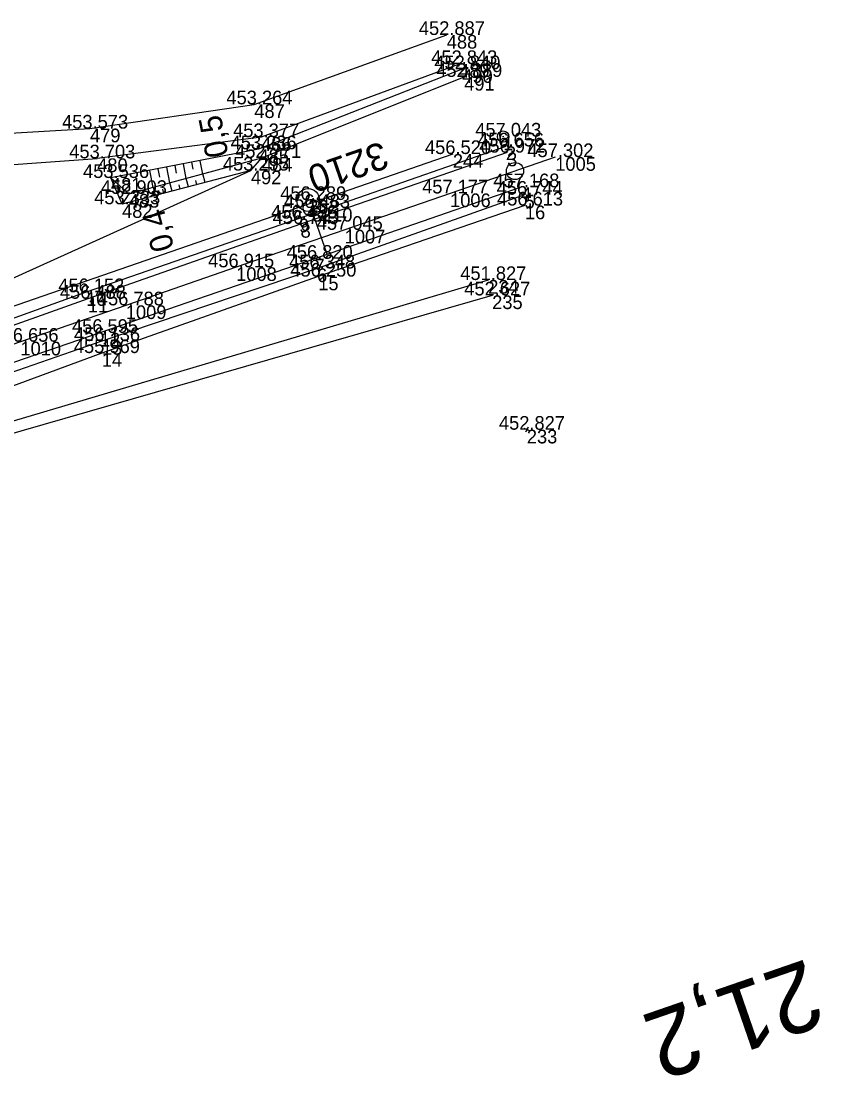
# Model space of a CAD drawing. Extents: x -751615 to -750797, y -1114905 to -1114561.
# Drawn here: x -750867.3 to -750797, y -1114657.1 to -1114564.4 of the extents above; entities that cross this region are included whole.
import ezdxf

# ---------------------------------------------------------------- set-up
doc = ezdxf.new("R2010")
doc.units = 0
for name, color, linetype in [('Vrstva 1', 7, 'Continuous'), ('Vrstva 4', 7, 'Continuous'), ('Vrstva 48', 7, 'Continuous'), ('Vrstva 49', 7, 'Continuous'), ('Vrstva 51', 7, 'Continuous'), ('Vrstva 60', 7, 'Continuous'), ('Vrstva 61', 7, 'Continuous'), ('Vrstva 63', 7, 'Continuous'), ('Vrstva 7', 7, 'Continuous')]:
    doc.layers.add(name, color=color, linetype=linetype)

msp = doc.modelspace()

# ---------------------------------------------------------------- linework, layer by layer
at = {"layer": 'Vrstva 1'}
msp.add_lwpolyline([(-750820.337, -1114576.326), (-750829.58, -1114579.518), (-750838.838, -1114582.712), (-750848.38, -1114586.005), (-750858.075, -1114589.346), (-750867.336, -1114592.541), (-750876.526, -1114595.715), (-750885.989, -1114598.98), (-750895.385, -1114602.229), (-750902.991, -1114604.843), (-750908.211, -1114606.647), (-750914.742, -1114608.898), (-750924.077, -1114612.114), (-750933.495, -1114615.368), (-750942.896, -1114618.61), (-750952.239, -1114621.829), (-750961.799, -1114625.127), (-750971.586, -1114628.505), (-750981.562, -1114631.945), (-750991.246, -1114635.286), (-751001.048, -1114638.665), (-751010.672, -1114641.989), (-751020.123, -1114645.246), (-751029.869, -1114648.612)], dxfattribs=at)
at = {"layer": 'Vrstva 4'}
for points in [[(-750824.673, -1114575.386), (-750842.852, -1114581.727), (-750861.561, -1114588.189), (-750880.945, -1114595.155), (-750899.361, -1114601.468), (-750902.908, -1114603.401)], [(-750824.563, -1114575.932), (-750842.715, -1114582.202), (-750861.411, -1114588.769), (-750880.904, -1114595.722), (-750899.175, -1114602.016), (-750902.908, -1114603.401)], [(-750823.32, -1114578.973), (-750841.487, -1114585.259), (-750860.348, -1114591.764), (-750879.972, -1114598.494), (-750898.231, -1114604.794), (-750901.922, -1114606.212)], [(-750823.034, -1114579.626), (-750841.271, -1114586.102), (-750860.173, -1114592.481), (-750879.743, -1114599.276), (-750897.921, -1114605.245), (-750901.922, -1114606.212)]]:
    msp.add_lwpolyline(points, dxfattribs=at)
at = {"layer": 'Vrstva 48'}
for p, q in [((-750853.039, -1114576.924), (-750852.79, -1114578.201)), ((-750852.302, -1114576.781), (-750852.183, -1114577.393)), ((-750851.566, -1114576.637), (-750851.338, -1114577.808)), ((-750855.983, -1114577.497), (-750855.693, -1114578.988)), ((-750855.247, -1114577.353), (-750855.107, -1114578.072)), ((-750854.511, -1114577.21), (-750854.242, -1114578.594)), ((-750853.775, -1114577.067), (-750853.645, -1114577.732)), ((-750851.11, -1114578.56), (-750851.308, -1114577.8)), ((-750854.013, -1114579.318), (-750854.204, -1114578.584)), ((-750853.287, -1114579.128), (-750853.384, -1114578.758)), ((-750852.561, -1114578.939), (-750852.756, -1114578.192)), ((-750851.836, -1114578.749), (-750851.934, -1114578.373)), ((-750855.464, -1114579.697), (-750855.652, -1114578.976)), ((-750854.738, -1114579.507), (-750854.833, -1114579.144))]:
    msp.add_line(p, q, dxfattribs=at)
at = {"layer": 'Vrstva 49'}
for p, q in [((-750857.81, -1114579.561), (-750846.11, -1114576.392)), ((-750822.608, -1114600.381), (-750823.058, -1114600.163)), ((-750822.724, -1114600.047), (-750822.942, -1114600.497))]:
    msp.add_line(p, q, dxfattribs=at)
for points in [[(-750828.513, -1114568.604), (-750846.414, -1114575.635), (-750859.378, -1114578.157)], [(-750902.869, -1114601.131), (-750876.43, -1114590.758), (-750847.082, -1114577.508), (-750846.11, -1114576.392), (-750828.341, -1114569.281)], [(-750829.333, -1114576.055), (-750875.877, -1114592.182), (-750902.869, -1114601.131)], [(-750847.082, -1114577.508), (-750858.403, -1114580.464), (-750859.378, -1114578.157)], [(-750859.378, -1114578.157), (-750857.81, -1114579.561), (-750858.403, -1114580.464)], [(-750823, -1114580.577), (-750841.163, -1114586.823), (-750860.183, -1114593.537), (-750879.382, -1114600.618), (-750897.603, -1114606.242), (-750900.708, -1114608.016), (-750901.423, -1114610.555), (-750897.925, -1114617.962)], [(-750826.229, -1114587.12), (-750875.492, -1114601.735), (-750898.314, -1114607.786)], [(-750825.879, -1114588.474), (-750875.252, -1114602.676), (-750897.922, -1114608.949)]]:
    msp.add_lwpolyline(points, dxfattribs=at)
at = {"layer": 'Vrstva 51'}
for points in [[(-750861.222, -1114573.82), (-750846.781, -1114571.689), (-750829.869, -1114565.596)], [(-750828.782, -1114568.15), (-750846.19, -1114574.573), (-750860.591, -1114576.435)], [(-750907.847, -1114605.676), (-750909.898, -1114596.967), (-750910.005, -1114587.848), (-750908.734, -1114583.94), (-750904.958, -1114578.749), (-750901.36, -1114576.145), (-750861.222, -1114573.82)], [(-750907.847, -1114605.676), (-750904.542, -1114604.506), (-750906.55, -1114596.602), (-750906.082, -1114588.417), (-750904.868, -1114585.385), (-750901.781, -1114581.531), (-750899.088, -1114579.21), (-750860.591, -1114576.435)]]:
    msp.add_lwpolyline(points, dxfattribs=at)
at = {"layer": 'Vrstva 60'}
for p, q in [((-750829.869, -1114565.596), (-750829.869, -1114565.596)), ((-750828.782, -1114568.15), (-750828.782, -1114568.15)), ((-750828.513, -1114568.604), (-750828.513, -1114568.604)), ((-750828.341, -1114569.281), (-750828.341, -1114569.281)), ((-750846.781, -1114571.689), (-750846.781, -1114571.689)), ((-750861.222, -1114573.82), (-750861.222, -1114573.82)), ((-750846.19, -1114574.573), (-750846.19, -1114574.573)), ((-750824.914, -1114574.521), (-750824.914, -1114574.521)), ((-750846.414, -1114575.635), (-750846.414, -1114575.635)), ((-750829.333, -1114576.055), (-750829.333, -1114576.055)), ((-750824.673, -1114575.386), (-750824.673, -1114575.386)), ((-750824.563, -1114575.932), (-750824.563, -1114575.932)), ((-750860.591, -1114576.435), (-750860.591, -1114576.435)), ((-750846.11, -1114576.392), (-750846.11, -1114576.392)), ((-750820.337, -1114576.326), (-750820.337, -1114576.326)), ((-750847.082, -1114577.508), (-750847.082, -1114577.508)), ((-750859.378, -1114578.157), (-750859.378, -1114578.157)), ((-750857.81, -1114579.561), (-750857.81, -1114579.561)), ((-750829.58, -1114579.518), (-750829.58, -1114579.518)), ((-750823.32, -1114578.973), (-750823.32, -1114578.973)), ((-750823.034, -1114579.626), (-750823.034, -1114579.626)), ((-750858.403, -1114580.464), (-750858.403, -1114580.464)), ((-750842.051, -1114580.092), (-750842.051, -1114580.092)), ((-750823, -1114580.577), (-750823, -1114580.577)), ((-750841.722, -1114580.791), (-750841.722, -1114580.791)), ((-750842.852, -1114581.727), (-750842.852, -1114581.727)), ((-750842.715, -1114582.202), (-750842.715, -1114582.202)), ((-750838.838, -1114582.712), (-750838.838, -1114582.712)), ((-750841.487, -1114585.259), (-750841.487, -1114585.259)), ((-750848.38, -1114586.005), (-750848.38, -1114586.005)), ((-750841.271, -1114586.102), (-750841.271, -1114586.102)), ((-750841.163, -1114586.823), (-750841.163, -1114586.823)), ((-750826.229, -1114587.12), (-750826.229, -1114587.12)), ((-750861.561, -1114588.189), (-750861.561, -1114588.189)), ((-750861.411, -1114588.769), (-750861.411, -1114588.769)), ((-750825.879, -1114588.474), (-750825.879, -1114588.474)), ((-750858.075, -1114589.346), (-750858.075, -1114589.346)), ((-750860.348, -1114591.764), (-750860.348, -1114591.764)), ((-750860.173, -1114592.481), (-750860.173, -1114592.481)), ((-750860.183, -1114593.537), (-750860.183, -1114593.537)), ((-750822.833, -1114600.272), (-750822.833, -1114600.272))]:
    msp.add_line(p, q, dxfattribs=at)
at = {"layer": 'Vrstva 63'}
for p, q in [((-750842.051, -1114580.092), (-750842.051, -1114580.092)), ((-750841.675, -1114580.775), (-750841.769, -1114580.807)), ((-750841.725, -1114581.037), (-750840.42, -1114584.818))]:
    msp.add_line(p, q, dxfattribs=at)
for centre, radius in [((-750842.051, -1114580.092), 1), ((-750841.722, -1114580.791), 0.756)]:
    msp.add_circle(centre, radius, dxfattribs=at)
at = {"layer": 'Vrstva 7'}
msp.add_line((-750824.867, -1114574.505), (-750824.961, -1114574.537), dxfattribs=at)
for centre, radius in [((-750824.914, -1114574.521), 0.5), ((-750823.872, -1114577.547), 0.75)]:
    msp.add_circle(centre, radius, dxfattribs=at)

# ---------------------------------------------------------------- texts
at = {"layer": 'Vrstva 48'}
for s, rotation, p in [('0,5', 101.00875, (-750849.039, -1114576.159)), ('0,4', 105.15521, (-750853.8, -1114584.322))]:
    msp.add_text(s, height=2, rotation=rotation, dxfattribs=at).set_placement(p)
at = {"layer": 'Vrstva 60'}
for s, p in [('488', (-750829.869, -1114566.796)), ('489', (-750828.782, -1114569.35)), ('490', (-750828.513, -1114569.804)), ('491', (-750828.341, -1114570.481)), ('487', (-750846.781, -1114572.889)), ('479', (-750861.222, -1114575.02)), ('486', (-750846.19, -1114575.773)), ('1', (-750824.914, -1114575.721)), ('485', (-750846.414, -1114576.835)), ('244', (-750829.333, -1114577.255)), ('2', (-750824.673, -1114576.586)), ('3', (-750824.563, -1114577.132)), ('480', (-750860.591, -1114577.635)), ('484', (-750846.11, -1114577.592)), ('1005', (-750820.337, -1114577.526)), ('492', (-750847.082, -1114578.708)), ('481', (-750859.378, -1114579.357)), ('483', (-750857.81, -1114580.761)), ('1006', (-750829.58, -1114580.718)), ('4', (-750823.32, -1114580.173)), ('5', (-750823.034, -1114580.826)), ('482', (-750858.403, -1114581.664)), ('232', (-750842.051, -1114581.292)), ('16', (-750823, -1114581.777)), ('3210', (-750841.722, -1114581.991)), ('9', (-750842.852, -1114582.927)), ('8', (-750842.715, -1114583.402)), ('1007', (-750838.838, -1114583.912)), ('7', (-750841.487, -1114586.459)), ('1008', (-750848.38, -1114587.205)), ('6', (-750841.271, -1114587.302)), ('15', (-750841.163, -1114588.023)), ('234', (-750826.229, -1114588.32)), ('10', (-750861.561, -1114589.389)), ('11', (-750861.411, -1114589.969)), ('235', (-750825.879, -1114589.674)), ('1009', (-750858.075, -1114590.546)), ('12', (-750860.348, -1114592.964)), ('1010', (-750867.336, -1114593.741)), ('13', (-750860.173, -1114593.681)), ('14', (-750860.183, -1114594.737)), ('233', (-750822.833, -1114601.472))]:
    msp.add_text(s, height=1.2, dxfattribs=at).set_placement(p)
at = {"layer": 'Vrstva 61'}
for s, p in [('452.887', (-750832.321, -1114565.596)), ('452.843', (-750831.234, -1114568.15)), ('452.840', (-750830.964, -1114568.604)), ('452.389', (-750830.795, -1114569.281)), ('453.264', (-750849.232, -1114571.689)), ('453.573', (-750863.674, -1114573.82)), ('453.377', (-750848.642, -1114574.573)), ('457.043', (-750827.366, -1114574.521)), ('456.656', (-750827.125, -1114575.386)), ('453.236', (-750848.866, -1114575.635)), ('456.520', (-750831.784, -1114576.055)), ('456.972', (-750827.011, -1114575.932)), ('457.302', (-750822.785, -1114576.326)), ('453.703', (-750863.043, -1114576.435)), ('452.771', (-750848.467, -1114576.392)), ('453.536', (-750861.83, -1114578.157)), ('453.295', (-750849.538, -1114577.508)), ('457.168', (-750825.774, -1114578.973)), ('452.903', (-750860.262, -1114579.561)), ('457.177', (-750832.032, -1114579.518)), ('456.744', (-750825.485, -1114579.626)), ('453.333', (-750860.855, -1114580.464)), ('456.289', (-750844.505, -1114580.092)), ('456.483', (-750844.174, -1114580.791)), ('456.613', (-750825.452, -1114580.577)), ('456.436', (-750845.304, -1114581.727)), ('456.743', (-750845.167, -1114582.202)), ('457.045', (-750841.294, -1114582.712)), ('456.820', (-750843.938, -1114585.259)), ('456.915', (-750850.836, -1114586.005)), ('456.348', (-750843.725, -1114586.102)), ('456.250', (-750843.614, -1114586.823)), ('451.827', (-750828.681, -1114587.12)), ('456.152', (-750864.009, -1114588.189)), ('456.488', (-750863.865, -1114588.769)), ('456.788', (-750860.529, -1114589.346)), ('452.627', (-750828.331, -1114588.474)), ('456.595', (-750862.804, -1114591.764)), ('456.656', (-750869.788, -1114592.541)), ('456.136', (-750862.625, -1114592.481)), ('455.969', (-750862.637, -1114593.537)), ('452.827', (-750825.285, -1114600.272))]:
    msp.add_text(s, height=1.2, dxfattribs=at).set_placement(p)
at = {"layer": 'Vrstva 63'}
msp.add_text('3210', height=2.4, rotation=199.0642, dxfattribs=at).set_placement((-750835.555, -1114574.908))
at = {"layer": 'Vrstva 7'}
msp.add_text('21,2', height=6, rotation=199.05196, dxfattribs=at).set_placement((-750798.218, -1114646.718))

doc.saveas('drawing.dxf')
